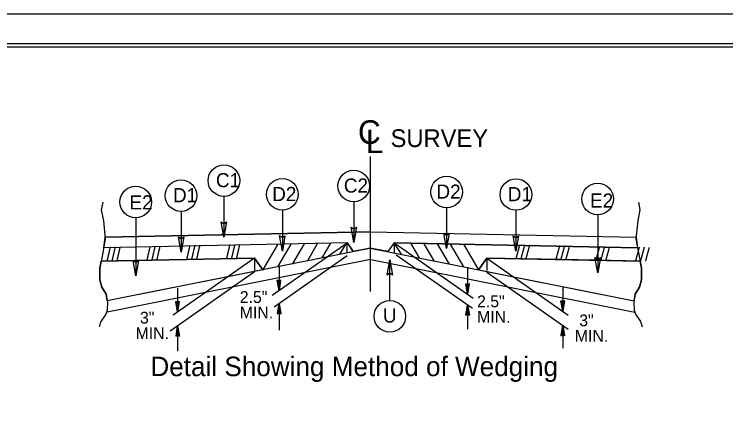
# Model space of a CAD drawing. Extents: x 575722 to 576066, y -53107 to -52774.
# Drawn here: x 575878.8 to 575932.7, y -53027.4 to -52996.9 of the extents above; entities that cross this region are included whole.
import ezdxf

# ---------------------------------------------------------------- set-up
doc = ezdxf.new("R2010")
doc.units = 0
for name, color, linetype in [('Prop DSN Text', 7, 'Continuous'), ('Sheet Cutting Line CELL', 7, 'Continuous'), ('Sheet Plot Border Inside CELL', 7, 'Continuous'), ('Sheet Plot Border Outside CELL', 7, 'Continuous'), ('Sheet Typical CELL', 7, 'Continuous')]:
    doc.layers.add(name, color=color, linetype=linetype)

msp = doc.modelspace()

# ---------------------------------------------------------------- linework, layer by layer
at = {"layer": 'Prop DSN Text'}
for p, q in [((575905.804, -53017.869), (575905.804, -53007.633)), ((575894.696, -53010.664), (575894.696, -53013.756)), ((575904.529, -53011.068), (575904.529, -53014.16)), ((575905.804, -53017.869), (575905.804, -53010.878)), ((575899.122, -53011.712), (575899.122, -53014.804)), ((575911.552, -53011.529), (575911.552, -53014.621)), ((575916.796, -53011.72), (575916.796, -53014.812)), ((575891.46, -53011.798), (575891.46, -53014.89)), ((575922.988, -53012.06), (575922.988, -53016.457)), ((575888.032, -53012.281), (575888.032, -53016.677)), ((575885.6, -53014.555), (575885.715, -53013.748)), ((575905.803, -53013.347), (575885.715, -53013.748)), ((575885.715, -53013.748), (575905.803, -53013.347)), ((575905.803, -53013.347), (575925.893, -53013.748)), ((575905.805, -53013.347), (575925.893, -53013.748)), ((575925.893, -53013.748), (575926.008, -53014.555)), ((575904.041, -53014.187), (575885.6, -53014.555)), ((575904.041, -53014.187), (575885.6, -53014.555)), ((575898.772, -53014.292), (575897.631, -53016.249)), ((575904.018, -53014.201), (575898.358, -53018.166)), ((575899.774, -53014.272), (575898.764, -53016.006)), ((575900.767, -53014.252), (575899.86, -53015.807)), ((575901.767, -53014.255), (575901.015, -53015.542)), ((575902.775, -53014.203), (575902.12, -53015.326)), ((575903.47, -53015.046), (575904.015, -53014.194)), ((575904.015, -53014.194), (575904.015, -53014.894)), ((575904.492, -53014.848), (575904.041, -53014.187)), ((575904.041, -53014.208), (575904.492, -53014.848)), ((575907.581, -53014.187), (575907.115, -53014.848)), ((575907.581, -53014.187), (575907.115, -53014.848)), ((575907.551, -53014.201), (575907.58, -53014.203)), ((575907.581, -53014.187), (575926.008, -53014.555)), ((575926.008, -53014.555), (575907.581, -53014.187)), ((575908.137, -53015.046), (575907.592, -53014.194)), ((575907.592, -53014.194), (575907.592, -53014.965)), ((575907.734, -53014.294), (575913.566, -53018.378)), ((575908.832, -53014.203), (575909.487, -53015.326)), ((575909.84, -53014.255), (575910.591, -53015.542)), ((575910.84, -53014.252), (575911.747, -53015.807)), ((575911.832, -53014.272), (575912.843, -53016.006)), ((575912.836, -53014.292), (575913.96, -53016.22)), ((575905.833, -53014.582), (575885.865, -53018.576)), ((575905.773, -53014.582), (575904.492, -53014.848)), ((575905.773, -53014.582), (575925.742, -53018.576)), ((575907.115, -53014.848), (575905.773, -53014.582)), ((575897.015, -53015.334), (575885.404, -53015.567)), ((575885.404, -53015.567), (575897.015, -53015.334)), ((575905.796, -53015.441), (575885.859, -53019.429)), ((575897.015, -53015.334), (575890.85, -53019.652)), ((575897.647, -53016.222), (575897.015, -53015.334)), ((575897.015, -53015.334), (575897.015, -53016.348)), ((575897.015, -53015.334), (575897.645, -53016.22)), ((575904.031, -53015.17), (575898.492, -53019.048)), ((575905.811, -53015.441), (575925.795, -53019.439)), ((575907.257, -53018.553), (575907.257, -53015.461)), ((575907.726, -53015.088), (575913.501, -53019.13)), ((575914.591, -53015.334), (575913.96, -53016.22)), ((575913.961, -53016.22), (575914.591, -53015.334)), ((575914.591, -53015.334), (575926.203, -53015.567)), ((575914.591, -53015.334), (575914.591, -53016.276)), ((575922.872, -53015.5), (575914.591, -53015.334)), ((575914.685, -53015.4), (575920.766, -53019.658)), ((575898.873, -53016.009), (575898.873, -53017.804)), ((575913.139, -53016.021), (575913.139, -53018.079)), ((575926.203, -53015.567), (575922.872, -53015.5)), ((575897.01, -53016.379), (575890.637, -53020.864)), ((575897.015, -53016.346), (575894.993, -53016.751)), ((575897.645, -53016.22), (575897.015, -53016.346)), ((575913.96, -53016.22), (575916.614, -53016.751)), ((575914.591, -53016.399), (575920.756, -53020.717)), ((575894.993, -53016.751), (575885.865, -53018.576)), ((575898.873, -53017.804), (575898.735, -53017.017)), ((575898.873, -53017.12), (575898.735, -53017.017)), ((575898.873, -53017.804), (575898.754, -53017.032)), ((575898.774, -53017.047), (575898.873, -53017.804)), ((575898.873, -53017.804), (575898.794, -53017.06)), ((575898.814, -53017.075), (575898.873, -53017.804)), ((575898.873, -53017.804), (575898.834, -53017.09)), ((575898.854, -53017.105), (575898.873, -53017.804)), ((575898.873, -53017.804), (575899.013, -53017.017)), ((575899.013, -53017.017), (575898.873, -53017.12)), ((575898.994, -53017.032), (575898.873, -53017.804)), ((575898.873, -53017.804), (575898.972, -53017.047)), ((575898.952, -53017.06), (575898.873, -53017.804)), ((575898.873, -53017.804), (575898.933, -53017.075)), ((575898.913, -53017.09), (575898.873, -53017.804)), ((575898.873, -53017.804), (575898.893, -53017.105)), ((575916.614, -53016.751), (575925.742, -53018.576)), ((575891.197, -53017.619), (575891.197, -53019.409)), ((575898.873, -53017.12), (575898.873, -53017.804)), ((575913.139, -53018.079), (575913.001, -53017.291)), ((575913.139, -53017.393), (575913.001, -53017.291)), ((575913.139, -53018.079), (575913.02, -53017.306)), ((575913.04, -53017.32), (575913.139, -53018.079)), ((575913.139, -53018.079), (575913.06, -53017.335)), ((575913.079, -53017.35), (575913.139, -53018.079)), ((575913.139, -53018.079), (575913.099, -53017.364)), ((575913.119, -53017.379), (575913.139, -53018.079)), ((575913.139, -53018.079), (575913.278, -53017.291)), ((575913.278, -53017.291), (575913.139, -53017.393)), ((575913.258, -53017.306), (575913.139, -53018.079)), ((575913.139, -53018.079), (575913.238, -53017.32)), ((575913.218, -53017.335), (575913.139, -53018.079)), ((575913.139, -53018.079), (575913.198, -53017.35)), ((575913.179, -53017.364), (575913.139, -53018.079)), ((575913.139, -53018.079), (575913.159, -53017.379)), ((575913.139, -53017.393), (575913.139, -53018.079)), ((575920.348, -53017.504), (575920.348, -53019.365)), ((575891.197, -53019.409), (575891.058, -53018.622)), ((575891.197, -53018.723), (575891.058, -53018.622)), ((575891.197, -53019.409), (575891.077, -53018.636)), ((575891.099, -53018.651), (575891.197, -53019.409)), ((575891.197, -53019.409), (575891.119, -53018.665)), ((575891.138, -53018.679), (575891.197, -53019.409)), ((575891.197, -53019.409), (575891.158, -53018.694)), ((575891.178, -53018.708), (575891.197, -53019.409)), ((575891.197, -53019.409), (575891.336, -53018.622)), ((575891.336, -53018.622), (575891.197, -53018.723)), ((575891.317, -53018.636), (575891.197, -53019.409)), ((575891.197, -53019.409), (575891.297, -53018.651)), ((575891.277, -53018.665), (575891.197, -53019.409)), ((575891.197, -53019.409), (575891.256, -53018.679)), ((575891.238, -53018.694), (575891.197, -53019.409)), ((575891.197, -53019.409), (575891.217, -53018.708)), ((575891.197, -53018.723), (575891.197, -53019.409)), ((575920.348, -53019.365), (575920.209, -53018.578)), ((575920.348, -53018.68), (575920.209, -53018.578)), ((575920.348, -53019.365), (575920.229, -53018.593)), ((575920.249, -53018.607), (575920.348, -53019.365)), ((575920.348, -53019.365), (575920.268, -53018.621)), ((575920.288, -53018.636), (575920.348, -53019.365)), ((575920.348, -53019.365), (575920.308, -53018.65)), ((575920.327, -53018.666), (575920.348, -53019.365)), ((575920.348, -53019.365), (575920.487, -53018.578)), ((575920.487, -53018.578), (575920.348, -53018.68)), ((575920.466, -53018.593), (575920.348, -53019.365)), ((575920.348, -53019.365), (575920.446, -53018.607)), ((575920.427, -53018.621), (575920.348, -53019.365)), ((575920.348, -53019.365), (575920.407, -53018.636)), ((575920.387, -53018.65), (575920.348, -53019.365)), ((575920.348, -53019.365), (575920.368, -53018.666)), ((575920.348, -53018.68), (575920.348, -53019.365)), ((575898.873, -53018.782), (575898.735, -53019.569)), ((575898.754, -53019.554), (575898.873, -53018.782)), ((575898.873, -53018.782), (575898.774, -53019.54)), ((575898.794, -53019.524), (575898.873, -53018.782)), ((575898.873, -53018.782), (575898.814, -53019.51)), ((575898.834, -53019.497), (575898.873, -53018.782)), ((575898.873, -53018.782), (575898.854, -53019.482)), ((575898.873, -53018.782), (575898.873, -53020.803)), ((575898.873, -53018.782), (575899.013, -53019.569)), ((575898.873, -53019.467), (575898.873, -53018.782)), ((575898.893, -53019.482), (575898.873, -53018.782)), ((575898.873, -53018.782), (575898.913, -53019.497)), ((575898.933, -53019.51), (575898.873, -53018.782)), ((575898.873, -53018.782), (575898.952, -53019.524)), ((575898.972, -53019.54), (575898.873, -53018.782)), ((575898.873, -53018.782), (575898.994, -53019.554)), ((575913.139, -53018.878), (575913.001, -53019.665)), ((575913.02, -53019.65), (575913.139, -53018.878)), ((575913.139, -53018.878), (575913.04, -53019.636)), ((575913.06, -53019.62), (575913.139, -53018.878)), ((575913.139, -53018.878), (575913.079, -53019.606)), ((575913.099, -53019.593), (575913.139, -53018.878)), ((575913.139, -53018.878), (575913.119, -53019.578)), ((575913.139, -53018.878), (575913.139, -53020.719)), ((575913.139, -53018.878), (575913.278, -53019.665)), ((575913.139, -53019.563), (575913.139, -53018.878)), ((575913.159, -53019.578), (575913.139, -53018.878)), ((575913.139, -53018.878), (575913.179, -53019.593)), ((575913.198, -53019.606), (575913.139, -53018.878)), ((575913.139, -53018.878), (575913.218, -53019.62)), ((575913.238, -53019.636), (575913.139, -53018.878)), ((575913.139, -53018.878), (575913.258, -53019.65)), ((575898.735, -53019.569), (575898.873, -53019.467)), ((575898.873, -53019.467), (575899.013, -53019.569)), ((575913.001, -53019.665), (575913.139, -53019.563)), ((575913.139, -53019.563), (575913.278, -53019.665)), ((575891.197, -53020.471), (575891.058, -53021.259)), ((575891.079, -53021.244), (575891.197, -53020.471)), ((575891.197, -53020.471), (575891.099, -53021.23)), ((575891.119, -53021.215), (575891.197, -53020.471)), ((575891.197, -53020.471), (575891.138, -53021.2)), ((575891.158, -53021.186), (575891.197, -53020.471)), ((575891.197, -53020.471), (575891.178, -53021.173)), ((575891.197, -53020.471), (575891.197, -53022.386)), ((575891.197, -53020.471), (575891.336, -53021.259)), ((575891.197, -53021.157), (575891.197, -53020.471)), ((575891.217, -53021.173), (575891.197, -53020.471)), ((575891.197, -53020.471), (575891.238, -53021.186)), ((575891.257, -53021.2), (575891.197, -53020.471)), ((575891.197, -53020.471), (575891.277, -53021.215)), ((575891.297, -53021.23), (575891.197, -53020.471)), ((575891.197, -53020.471), (575891.317, -53021.244)), ((575920.348, -53020.43), (575920.209, -53021.218)), ((575920.229, -53021.203), (575920.348, -53020.43)), ((575920.348, -53020.43), (575920.249, -53021.188)), ((575920.268, -53021.174), (575920.348, -53020.43)), ((575920.348, -53020.43), (575920.288, -53021.159)), ((575920.308, -53021.144), (575920.348, -53020.43)), ((575920.348, -53020.43), (575920.327, -53021.13)), ((575920.348, -53020.43), (575920.348, -53022.159)), ((575920.348, -53020.43), (575920.487, -53021.218)), ((575920.348, -53021.114), (575920.348, -53020.43)), ((575920.368, -53021.13), (575920.348, -53020.43)), ((575920.348, -53020.43), (575920.387, -53021.144)), ((575920.407, -53021.159), (575920.348, -53020.43)), ((575920.348, -53020.43), (575920.427, -53021.174)), ((575920.446, -53021.188), (575920.348, -53020.43)), ((575920.348, -53020.43), (575920.466, -53021.203)), ((575891.058, -53021.259), (575891.197, -53021.157)), ((575891.197, -53021.157), (575891.336, -53021.259)), ((575920.209, -53021.218), (575920.348, -53021.114)), ((575920.348, -53021.114), (575920.487, -53021.218))]:
    msp.add_line(p, q, dxfattribs=at)
for points in [[(575885.528, -53011.097), (575885.421, -53011.685), (575885.582, -53012.522), (575885.724, -53013.876), (575885.528, -53014.946), (575885.297, -53016.104), (575885.314, -53016.978), (575885.457, -53017.529), (575885.778, -53018.082), (575885.885, -53018.688), (575885.867, -53019.294), (575885.76, -53019.579), (575885.386, -53020.149), (575885.261, -53020.542)], [(575926.079, -53011.097), (575926.186, -53011.685), (575926.026, -53012.522), (575925.883, -53013.876), (575926.079, -53014.946), (575926.311, -53016.104), (575926.293, -53016.978), (575926.15, -53017.529), (575925.829, -53018.082), (575925.723, -53018.688), (575925.74, -53019.294), (575925.847, -53019.579), (575926.221, -53020.149), (575926.345, -53020.542)], [(575885.865, -53018.576), (575885.778, -53018.082), (575885.457, -53017.529), (575885.314, -53016.978), (575885.297, -53016.104), (575885.404, -53015.567)], [(575925.742, -53018.576), (575925.829, -53018.082), (575926.15, -53017.529), (575926.293, -53016.978), (575926.311, -53016.104), (575926.203, -53015.567)]]:
    msp.add_lwpolyline(points, dxfattribs=at)
for points in [[(575894.895, -53012.596), (575894.696, -53013.756), (575894.489, -53012.589), (575894.696, -53012.737)], [(575894.895, -53012.596), (575894.696, -53013.756), (575894.489, -53012.589), (575894.696, -53012.737)], [(575904.729, -53013), (575904.529, -53014.16), (575904.323, -53012.994), (575904.529, -53013.142)], [(575904.729, -53013), (575904.529, -53014.16), (575904.323, -53012.994), (575904.529, -53013.142)], [(575891.659, -53013.73), (575891.46, -53014.89), (575891.253, -53013.724), (575891.46, -53013.872)], [(575891.659, -53013.73), (575891.46, -53014.89), (575891.253, -53013.724), (575891.46, -53013.872)], [(575899.321, -53013.644), (575899.122, -53014.804), (575898.915, -53013.637), (575899.122, -53013.786)], [(575899.321, -53013.644), (575899.122, -53014.804), (575898.915, -53013.637), (575899.122, -53013.786)], [(575911.752, -53013.461), (575911.552, -53014.621), (575911.346, -53013.455), (575911.552, -53013.603)], [(575911.752, -53013.461), (575911.552, -53014.621), (575911.346, -53013.455), (575911.552, -53013.603)], [(575916.996, -53013.652), (575916.796, -53014.812), (575916.59, -53013.646), (575916.796, -53013.794)], [(575916.996, -53013.652), (575916.796, -53014.812), (575916.59, -53013.646), (575916.796, -53013.794)], [(575907.057, -53016.621), (575907.257, -53015.461), (575907.463, -53016.628), (575907.257, -53016.48)], [(575907.057, -53016.621), (575907.257, -53015.461), (575907.463, -53016.628), (575907.257, -53016.48)], [(575923.188, -53015.297), (575922.988, -53016.457), (575922.782, -53015.29), (575922.988, -53015.439)], [(575888.232, -53015.517), (575888.032, -53016.677), (575887.826, -53015.511), (575888.032, -53015.659)], [(575888.232, -53015.517), (575888.032, -53016.677), (575887.826, -53015.511), (575888.032, -53015.659)]]:
    msp.add_lwpolyline(points, close=True, dxfattribs=at)
for centre in [(575894.696, -53009.467), (575904.529, -53009.872), (575891.459, -53010.602), (575899.122, -53010.516), (575911.553, -53010.333), (575916.796, -53010.524), (575888.031, -53011.085), (575922.987, -53010.864), (575907.257, -53019.75)]:
    msp.add_circle(centre, 1.196, dxfattribs=at)
at = {"layer": 'Sheet Cutting Line CELL'}
msp.add_line((575965.78, -52996.867), (575797.38, -52996.867), dxfattribs=at)
at = {"layer": 'Sheet Plot Border Inside CELL'}
msp.add_lwpolyline([(575965.33, -52999.112), (575798.68, -52999.112), (575798.68, -53104.622), (575965.33, -53104.622)], close=True, dxfattribs=at)
at = {"layer": 'Sheet Plot Border Outside CELL'}
msp.add_lwpolyline([(575965.78, -52996.867), (575797.38, -52996.867), (575797.38, -53106.867), (575965.78, -53106.867)], close=True, dxfattribs=at)
at = {"layer": 'Sheet Typical CELL'}
msp.add_lwpolyline([(575964.08, -52999.367), (575814.08, -52999.367), (575814.08, -53104.367), (575964.08, -53104.367)], close=True, dxfattribs=at)

# ---------------------------------------------------------------- texts
at = {"layer": 'Prop DSN Text'}
for s, height, p in [('C', 1.79, (575904.843, -53006.687)), ('L', 1.79, (575905.444, -53007.39)), ('SURVEY ', 1.3422, (575907.314, -53006.927)), ('C1', 1.0708, (575894.096, -53009.972)), ('C2', 1.0708, (575903.776, -53010.378)), ('D1', 1.0708, (575890.844, -53011.108)), ('D2', 1.0708, (575898.353, -53011.022)), ('D2', 1.0708, (575910.784, -53010.839)), ('D1', 1.0708, (575916.181, -53011.03)), ('E2', 1.0708, (575887.551, -53011.654)), ('E2', 1.0708, (575922.406, -53011.516)), ('2.5"', 0.8948, (575895.902, -53018.736)), ('2.5"', 0.8948, (575913.86, -53019.064)), ('MIN.', 0.8948, (575895.902, -53019.909)), ('U', 1.071, (575906.734, -53020.223)), (' 3"', 0.8948, (575888.015, -53020.299)), ('MIN.', 0.8948, (575913.86, -53020.237)), (' 3"', 0.8948, (575921.259, -53020.505)), ('MIN.', 0.8948, (575888.015, -53021.472)), ('MIN.', 0.8948, (575921.259, -53021.678)), ('Detail Showing Method of Wedging', 1.47703, (575889.136, -53024.282))]:
    msp.add_text(s, height=height, dxfattribs=at).set_placement(p)
for height, rotation, p in [(1.007, 1.1445, (575891.832, -53015.429)), (1.0071, 1.1463, (575894.853, -53015.367)), (1.0071, 358.8553, (575916.754, -53015.367)), (1.007, 358.8536, (575919.775, -53015.429)), (1.0074, 1.1447, (575885.804, -53015.553)), (1.0074, 1.1464, (575888.815, -53015.517)), (1.0074, 358.8554, (575922.792, -53015.517)), (1.0074, 358.8537, (575925.803, -53015.553))]:
    msp.add_text('/// ', height=height, rotation=rotation, dxfattribs=at).set_placement(p)

doc.saveas('drawing.dxf')
